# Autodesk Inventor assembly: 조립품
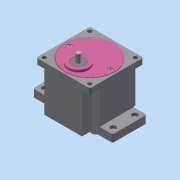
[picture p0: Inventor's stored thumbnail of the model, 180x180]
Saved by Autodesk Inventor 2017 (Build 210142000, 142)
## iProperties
Part Number: 조립품
Material: 일반
Document SubType Name: Assembly
Designer: user
Author: user
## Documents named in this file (10)
- C:\Users\user\Desktop\700116V1008\조립품.iam
- C:\Users\user\Desktop\700116V1008\메인 축.ipt
- C:\Users\user\Desktop\700116V1008\베어링 608.ipt
- C:\Users\user\Desktop\700116V1008\베어링 6003.ipt
- C:\Users\user\Desktop\700116V1008\본체.ipt
- C:\Users\user\Desktop\700116V1008\볼트 M4.ipt
- C:\Users\user\Desktop\700116V1008\서브 축.ipt
- C:\Users\user\Desktop\700116V1008\오일 실 8 22 7.ipt
- C:\Users\user\Desktop\700116V1008\오일 실 17 32 8.ipt
- C:\Users\user\Desktop\700116V1008\커버.ipt
